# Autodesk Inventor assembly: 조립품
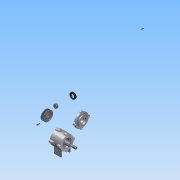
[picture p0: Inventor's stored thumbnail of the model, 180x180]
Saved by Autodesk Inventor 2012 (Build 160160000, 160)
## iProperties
Created: 2015-03
Part Number: 조립품
Document SubType Name: Assembly
Designer: net
Author: net
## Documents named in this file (11)
- C:\Users\net\Desktop\450305V1049\조립품.iam
- C:\Users\net\Documents\Inventor\450305V1049\본체.ipt
- C:\Users\net\Desktop\450305V1049\커버.ipt
- C:\Users\net\Desktop\450305V1049\커버2.ipt
- C:\Users\net\Desktop\450305V1049\M 4 x 12.ipt
- C:\Users\net\Desktop\450305V1049\V벨트풀리.ipt
- C:\Users\net\Desktop\450305V1049\너트 M12x1.25.ipt
- C:\Users\net\Desktop\450305V1049\베어링 6204.ipt
- C:\Users\net\Desktop\450305V1049\오일실.ipt
- C:\Users\net\Desktop\450305V1049\축.ipt
- C:\Users\net\Desktop\450305V1049\키(4 x 4 x 12).ipt
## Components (7 placed, 6 different names)
1. KS B 1003 - 미터 M 4 x 12:1
2. 그루브 풀리1:1
3. KS B 1012 클래스 1 일반 - 미터 M12x1.25:1
4. KS B 2023 6204 - 20 x 47 x 14:1
5. KS B 2804 D D - 20 32 8:1
6. KS B 1311 (I) 4 x 4 x 12:1
7. KS B 2023 6204 - 20 x 47 x 14:2
